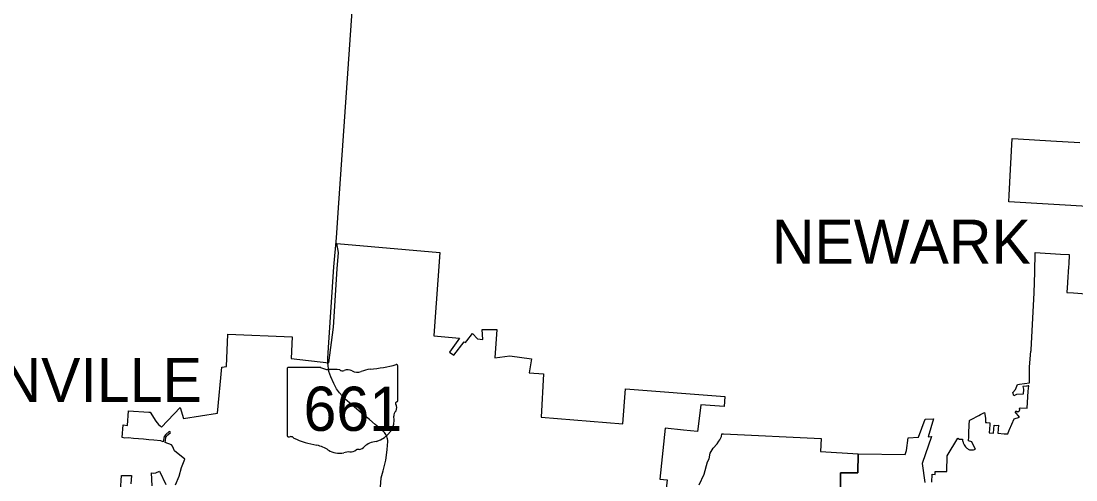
# Model space of a CAD drawing. Extents: x 1853412 to 2125412, y 679418 to 855418.
# Drawn here: x 1954732 to 1981493, y 753951 to 765585 of the extents above; entities that cross this region are included whole.
import ezdxf

# ---------------------------------------------------------------- set-up
doc = ezdxf.new("R2010")
doc.units = 0
for name, color, linetype in [('GM_X_Corporation', 7, 'Continuous'), ('GM_X_Corporation_Text', 7, 'Continuous'), ('GM_X_State_Location', 7, 'Continuous'), ('GM_X_State_Route', 7, 'Continuous'), ('GM_X_State_Shield', 7, 'Continuous')]:
    doc.layers.add(name, color=color, linetype=linetype)

msp = doc.modelspace()

# ---------------------------------------------------------------- linework, layer by layer
at = {"layer": 'GM_X_Corporation'}
for points in [[(1981931, 760876), (1979795, 761003), (1979804, 761175), (1979837, 761825), (1979877, 762607), (1980025, 762599), (1980855, 762551), (1981591, 762509)], [(1958652, 753826), (1958739, 754042), (1958799, 754262), (1958890, 754478), (1958621, 754689), (1958573, 754802), (1958548, 754838), (1958385, 754900), (1958394, 754961), (1958406, 755024), (1958408, 755041), (1958418, 755053), (1958432, 755071), (1958456, 755094), (1958523, 755156), (1958485, 755174), (1958406, 755098), (1958370, 755063), (1958360, 755048), (1958337, 754920), (1958274, 754941), (1958102, 754959), (1957969, 754969), (1957834, 754983), (1957588, 755004), (1957461, 755015), (1957364, 755013), (1957297, 755029), (1957325, 755345), (1957429, 755334), (1957456, 755705), (1957975, 755671), (1958007, 755669), (1958152, 755439), (1958220, 755359), (1958257, 755321), (1958296, 755292), (1958764, 755788), (1958855, 755506), (1959715, 755639), (1959824, 756812), (1959945, 756825), (1959979, 757647), (1961609, 757580), (1961586, 757026), (1962538, 756919), (1962657, 757825), (1962755, 759300), (1962783, 759721), (1962745, 759946), (1965359, 759717), (1965214, 757728), (1965205, 757603), (1965857, 757546), (1965602, 757191), (1965709, 757110), (1965977, 757456), (1966005, 757434), (1966040, 757479), (1966187, 757660), (1966308, 757530), (1966443, 757510), (1966432, 757761), (1966798, 757766), (1966752, 757050), (1967134, 757101), (1967679, 757022), (1967625, 756666), (1967985, 756643), (1967930, 755543), (1969999, 755369), (1970068, 756260), (1972589, 756065), (1972566, 755816), (1971977, 755852), (1971945, 755576), (1971897, 755176), (1971536, 755212), (1971075, 755259), (1970941, 753972), (1971123, 753954), (1971065, 753438)], [(1977840, 753892), (1977844, 754092), (1977919, 754090), (1977920, 754165), (1978220, 754160), (1978227, 754560), (1978495, 755009), (1978543, 754985), (1978616, 754983), (1978620, 754954), (1978624, 754926), (1978630, 754908), (1978635, 754892), (1978643, 754874), (1978659, 754842), (1978678, 754811), (1978692, 754793), (1978706, 754776), (1978725, 754757), (1978742, 754744), (1978757, 754734), (1978775, 754725), (1978797, 754717), (1978819, 754712), (1978846, 754710), (1978869, 754711), (1978893, 754715), (1978918, 754723), (1978943, 754733), (1978865, 754889), (1978853, 754912), (1978769, 754938), (1978774, 755047), (1978779, 755177), (1978785, 755306), (1978787, 755345), (1978791, 755455), (1978800, 755462), (1978870, 755500), (1978887, 755509), (1978979, 755559), (1979028, 755586), (1979072, 755610), (1979170, 755663), (1979197, 755513), (1979197, 755404), (1979237, 755403), (1979311, 755397), (1979307, 755348), (1979295, 755147), (1979406, 755140), (1979417, 755338), (1979480, 755334), (1979527, 755335), (1979516, 755133), (1979676, 755123), (1979766, 755117), (1979801, 755215), (1979806, 755226), (1979867, 755367), (1979924, 755498), (1979926, 755499), (1980065, 755542), (1979950, 755679), (1979963, 755689), (1979969, 755693), (1979980, 755694), (1979987, 755693), (1979995, 755688), (1980007, 755683), (1980020, 755681), (1980032, 755682), (1980042, 755686), (1980051, 755692), (1980063, 755708), (1980066, 755717), (1980068, 755727), (1980068, 755733), (1980066, 755742), (1980060, 755755), (1980056, 755761), (1980079, 755776), (1980254, 755767), (1980286, 756197), (1980296, 756336), (1980281, 756333), (1980258, 756328), (1980240, 756325), (1980150, 756316), (1980165, 756251), (1980157, 756125), (1979990, 756120), (1979916, 756081), (1979896, 756165), (1979961, 756246), (1980008, 756369), (1980065, 756378), (1980316, 756414), (1980316, 756817), (1980347, 757212), (1980361, 757220), (1980362, 757249), (1980433, 758695), (1980448, 759217), (1980463, 759721), (1981104, 759679), (1981324, 759665), (1981310, 759424), (1981306, 759353), (1981282, 758964), (1981281, 758947), (1981265, 758704), (1981428, 758692), (1981752, 758668)], [(1975520, 752141), (1975520, 754131), (1975960, 754131), (1975969, 754612), (1977158, 754597), (1977191, 754693), (1977238, 755017), (1977502, 755038), (1977666, 755494), (1977884, 755502), (1977742, 755046), (1977832, 755052), (1977590, 754366), (1977657, 753888)], [(1971937, 753823), (1972060, 754098), (1972145, 754410), (1972185, 754487), (1972218, 754626), (1972291, 754758), (1972389, 754869), (1972437, 754929), (1972458, 754964), (1972503, 755048), (1972514, 755121), (1972551, 755121), (1975034, 754998), (1975015, 754673), (1975969, 754612), (1975960, 754131), (1975520, 754131), (1975520, 752141)], [(1958057, 753802), (1958042, 754131), (1958099, 754122), (1958152, 754134), (1958246, 754173), (1958408, 753833)], [(1957255, 753674), (1957282, 754062), (1957535, 754061), (1957516, 753849)]]:
    msp.add_lwpolyline(points, dxfattribs=at)
at = {"layer": 'GM_X_State_Route'}
for points in [[(1962539, 757434), (1962665, 759353), (1962733, 760092), (1962787, 760848), (1963232, 767308), (1963289, 768375), (1963308, 768763), (1963339, 769485), (1963353, 770210)], [(1962512, 756964), (1962511, 756970), (1962513, 757034), (1962539, 757434)], [(1962542, 756701), (1962515, 756919), (1962512, 756964)], [(1963368, 755645), (1963179, 755803), (1962945, 756006), (1962813, 756155), (1962736, 756261), (1962664, 756397), (1962589, 756562), (1962542, 756701)], [(1963847, 755253), (1963797, 755291), (1963719, 755356), (1963574, 755481), (1963408, 755612), (1963368, 755645)], [(1963806, 753146), (1963833, 753598), (1963862, 753877), (1963864, 754004), (1963917, 754180), (1963985, 754450), (1964005, 754574), (1964023, 754723), (1964033, 754924), (1964034, 754948), (1964029, 754990), (1964020, 755021), (1964010, 755053), (1963997, 755079), (1963984, 755102), (1963968, 755124), (1963952, 755149), (1963927, 755175), (1963896, 755206), (1963847, 755253)]]:
    msp.add_lwpolyline(points, dxfattribs=at)
at = {"layer": 'GM_X_State_Shield'}
for p, q in [((1962333, 756804), (1961513, 756804)), ((1964287, 755957), (1964287, 756847)), ((1961485, 756775), (1961485, 755074)), ((1964286, 755957), (1964287, 755957))]:
    msp.add_line(p, q, dxfattribs=at)
for centre, major_axis, start_param, end_param in [((1961517, 756779), (32.5, 0), 1.712693, 3.28349), ((1962528, 757002), (315, 0), 4.042523, 4.731795), ((1963289, 759124), (2971, 0), 4.814394, 5.042369), ((1964256, 756850), (31.2, 0), 6.141152, 7.989035), ((1962633, 755849), (1130, 0), 1.404758, 1.657858), ((1962889, 756788), (90.8, 0), 3.836095, 5.185415), ((1963023, 756591), (189, 0), 0.950623, 2.079405), ((1963267, 756861), (227, 0), 4.081561, 5.145723), ((1963668, 756285), (598, 0), 1.699011, 2.107814), ((1964280, 755891), (48.3, 0), 1.883978, 3.671073), ((1963972, 755779), (290, 0), 5.934695, 6.695948), ((1964253, 755953), (33.4, 0), 5.05454, 6.418171), ((1963455, 755471), (743, 0), 5.101752, 6.440018), ((1964398, 755584), (211, 0), 2.387724, 3.262537), ((1961517, 755070), (32.7, 0), 3.00124, 4.508301), ((1961522, 755244), (250, 0), 4.665946, 4.897461), ((1961573, 754976), (90.1, 0), 0.519207, 1.627899), ((1962711, 756504), (2146, 0), 4.195997, 4.488961), ((1963769, 754596), (407, 0), 1.647645, 2.488434), ((1962071, 754310), (671, 0), 0.823519, 1.323587), ((1962797, 754967), (426, 0), 4.026481, 4.996735), ((1963044, 754379), (350, 0), 1.495662, 1.94098), ((1963075, 754840), (227, 0), 4.691044, 5.507374), ((1963280, 754675), (63.9, 0), 1.147584, 2.315152), ((1963253, 754909), (240, 0), 4.937069, 5.64225)]:
    msp.add_ellipse(centre, major_axis=major_axis, ratio=0.8, start_param=start_param, end_param=end_param, dxfattribs=at)

# ---------------------------------------------------------------- texts
at = {"layer": 'GM_X_Corporation_Text'}
for s, p in [('NEWARK', (1973778, 759430)), ('GRANVILLE', (1950913, 755925))]:
    msp.add_text(s, height=1120, rotation=0, dxfattribs=at).set_placement(p)
at = {"layer": 'GM_X_State_Location'}
msp.add_text('661', height=1, rotation=0, dxfattribs=at).set_placement((1962475, 755884))
for s in ['s', 'r']:
    msp.add_text(s, height=1, dxfattribs=at).set_placement((1962828, 755957))
at = {"layer": 'GM_X_State_Shield'}
msp.add_text('661', height=1120.7, dxfattribs=at).set_placement((1961898, 755194))

doc.saveas('drawing.dxf')
